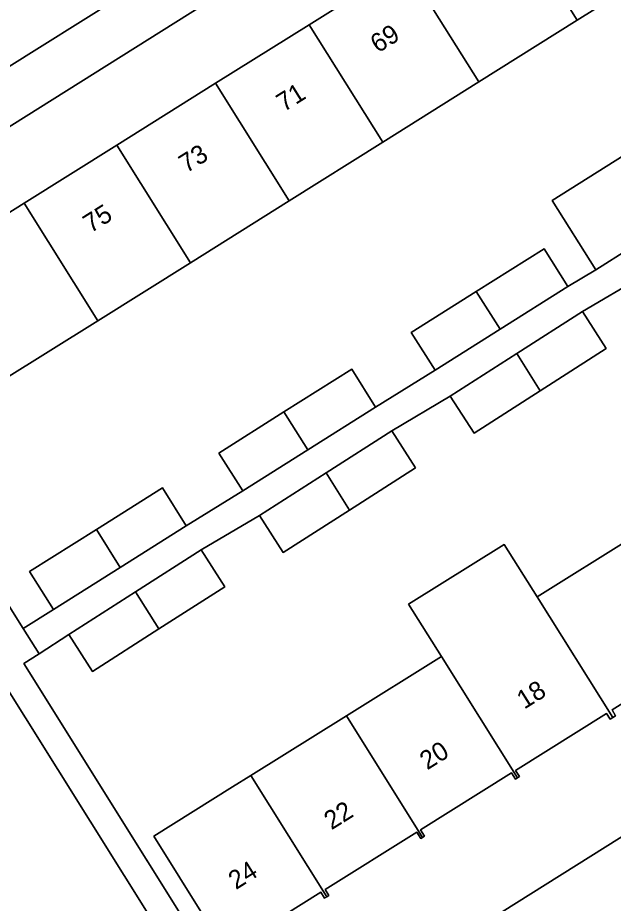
# Model space of a CAD drawing. Extents: x 160077 to 160948, y 386481 to 387498.
# Drawn here: x 160267.39 to 160299.46, y 387095.89 to 387143.58 of the extents above; entities that cross this region are included whole.
import ezdxf

# ---------------------------------------------------------------- set-up
doc = ezdxf.new("R2010")
doc.units = 0
for name, color, linetype in [('IMGEO_Erf', 7, 'Continuous'), ('IMGEO_Groenvoorziening', 7, 'Continuous'), ('IMGEO_Pand', 7, 'Continuous'), ('IMGEO_Pand_nummerreeks', 7, 'Continuous'), ('IMGEO_Parkeervlak_open', 7, 'Continuous'), ('IMGEO_Voetpad_open', 7, 'Continuous')]:
    doc.layers.add(name, color=color, linetype=linetype)

msp = doc.modelspace()

# ---------------------------------------------------------------- linework, layer by layer
at = {"layer": 'IMGEO_Erf'}
for points in [[(160296.499, 387156.3), (160255.281, 387130.409), (160257.386, 387127.102), (160262.53, 387130.326), (160267.734, 387133.588), (160272.723, 387136.714), (160278.049, 387140.052), (160283.079, 387143.205), (160288.249, 387146.446)], [(160302.552, 387146.604), (160297.518, 387143.449), (160292.212, 387140.123), (160287.042, 387136.883), (160282.011, 387133.73), (160276.686, 387130.392), (160271.698, 387127.266), (160266.493, 387124.003)], [(160261.349, 387120.779), (160267.688, 387110.692), (160269.311, 387111.715), (160268.027, 387113.752), (160271.626, 387116.021), (160275.184, 387118.265), (160276.468, 387116.228), (160279.504, 387118.104), (160278.22, 387120.141), (160281.726, 387122.352), (160285.377, 387124.654), (160286.661, 387122.617), (160289.86, 387124.595), (160288.576, 387126.632), (160292.082, 387128.843), (160295.733, 387131.145), (160297.017, 387129.108), (160298.519, 387130.015), (160296.174, 387133.735), (160301.501, 387137.095)], [(160300.981, 387129.632), (160297.804, 387127.766), (160299.081, 387125.774), (160295.522, 387123.491), (160291.96, 387121.206), (160290.683, 387123.197), (160287.534, 387121.342), (160288.811, 387119.35), (160285.252, 387117.067), (160281.69, 387114.782), (160280.413, 387116.773), (160277.266, 387114.933), (160278.543, 387112.941), (160274.998, 387110.667), (160271.422, 387108.373), (160270.145, 387110.364), (160268.541, 387109.335), (160267.725, 387108.811), (160280.982, 387087.594), (160343.569, 387126.901)], [(160278.833, 387092.92), (160274.718, 387099.506), (160278.959, 387102.156), (160279.935, 387102.766), (160285.087, 387105.985), (160290.2, 387109.18), (160288.434, 387111.995), (160293.59, 387115.217), (160295.356, 387112.402), (160300.473, 387115.599)], [(160304.261, 387109.353), (160299.391, 387106.304), (160299.584, 387105.994), (160299.435, 387105.901), (160299.285, 387105.807), (160299.092, 387106.116), (160294.195, 387103.05), (160294.406, 387102.714), (160294.298, 387102.647), (160294.189, 387102.579), (160293.979, 387102.915), (160289.08, 387099.848), (160289.293, 387099.507), (160289.191, 387099.444), (160289.092, 387099.382), (160288.879, 387099.722), (160283.944, 387096.633), (160284.145, 387096.31), (160284.03, 387096.238), (160283.916, 387096.167), (160283.715, 387096.49), (160278.842, 387093.439)]]:
    msp.add_lwpolyline(points, dxfattribs=at)
at = {"layer": 'IMGEO_Groenvoorziening'}
msp.add_lwpolyline([(160250.939, 387127.668), (160246.937, 387125.176), (160273.417, 387082.895), (160277.504, 387085.429), (160277.697, 387085.561), (160277.877, 387085.709), (160278.043, 387085.873), (160278.194, 387086.051), (160278.329, 387086.242), (160278.445, 387086.444), (160278.544, 387086.656), (160278.623, 387086.876), (160278.682, 387087.102), (160278.72, 387087.332), (160278.738, 387087.565), (160278.735, 387087.798), (160278.712, 387088.03), (160278.667, 387088.26), (160278.602, 387088.484), (160278.518, 387088.702), (160278.414, 387088.911), (160278.341, 387089.035), (160266.048, 387108.664)], dxfattribs=at)
at = {"layer": 'IMGEO_Pand'}
for points in [[(160298.589, 387152.926), (160293.555, 387149.771), (160297.518, 387143.449), (160302.552, 387146.604)], [(160292.212, 387140.123), (160297.518, 387143.449), (160293.555, 387149.771), (160288.249, 387146.446)], [(160287.042, 387136.883), (160292.212, 387140.123), (160288.249, 387146.446), (160283.079, 387143.205)], [(160283.079, 387143.205), (160278.049, 387140.052), (160282.011, 387133.73), (160287.042, 387136.883)], [(160276.686, 387130.392), (160282.011, 387133.73), (160278.049, 387140.052), (160272.723, 387136.714)], [(160303.837, 387133.369), (160302.558, 387135.409), (160301.501, 387137.095), (160296.174, 387133.735), (160298.519, 387130.015), (160300.336, 387131.161)], [(160272.723, 387136.714), (160267.734, 387133.588), (160271.698, 387127.266), (160276.686, 387130.392)], [(160266.493, 387124.003), (160271.698, 387127.266), (160267.734, 387133.588), (160262.53, 387130.326)], [(160297.017, 387129.108), (160295.733, 387131.145), (160292.082, 387128.843), (160293.361, 387126.803)], [(160288.576, 387126.632), (160289.86, 387124.595), (160293.361, 387126.803), (160292.082, 387128.843)], [(160299.081, 387125.774), (160297.804, 387127.766), (160294.265, 387125.495), (160295.522, 387123.491)], [(160290.683, 387123.197), (160291.96, 387121.206), (160295.522, 387123.491), (160294.265, 387125.495)], [(160286.661, 387122.617), (160285.377, 387124.654), (160281.726, 387122.352), (160283.005, 387120.312)], [(160278.22, 387120.141), (160279.504, 387118.104), (160283.005, 387120.312), (160281.726, 387122.352)], [(160288.811, 387119.35), (160287.534, 387121.342), (160283.995, 387119.071), (160285.252, 387117.067)], [(160280.413, 387116.773), (160281.69, 387114.782), (160285.252, 387117.067), (160283.995, 387119.071)], [(160272.905, 387113.981), (160276.468, 387116.228), (160275.184, 387118.265), (160271.626, 387116.021)], [(160271.626, 387116.021), (160268.027, 387113.752), (160269.311, 387111.715), (160272.905, 387113.981)], [(160300.473, 387115.599), (160295.356, 387112.402), (160299.435, 387105.901), (160299.584, 387105.994), (160299.391, 387106.304), (160304.261, 387109.353), (160304.441, 387109.065), (160304.535, 387109.124)], [(160274.998, 387110.667), (160278.543, 387112.941), (160277.266, 387114.933), (160273.741, 387112.671)], [(160295.356, 387112.402), (160293.59, 387115.217), (160288.434, 387111.995), (160290.2, 387109.18), (160294.298, 387102.647), (160294.406, 387102.714), (160294.195, 387103.05), (160299.092, 387106.116), (160299.285, 387105.807), (160299.435, 387105.901)], [(160273.741, 387112.671), (160270.145, 387110.364), (160271.422, 387108.373), (160274.998, 387110.667)], [(160290.2, 387109.18), (160285.087, 387105.985), (160289.191, 387099.444), (160289.293, 387099.507), (160289.08, 387099.848), (160293.979, 387102.915), (160294.189, 387102.579), (160294.298, 387102.647)], [(160285.087, 387105.985), (160279.935, 387102.766), (160284.03, 387096.238), (160284.145, 387096.31), (160283.944, 387096.633), (160288.879, 387099.722), (160289.092, 387099.382), (160289.191, 387099.444)], [(160279.935, 387102.766), (160278.959, 387102.156), (160274.718, 387099.506), (160278.833, 387092.92), (160279.073, 387093.07), (160278.842, 387093.439), (160283.715, 387096.49), (160283.916, 387096.167), (160284.03, 387096.238)]]:
    msp.add_lwpolyline(points, close=True, dxfattribs=at)
at = {"layer": 'IMGEO_Parkeervlak_open'}
msp.add_lwpolyline([(160262.765, 387147.16), (160266.781, 387140.866), (160272.691, 387144.583)], dxfattribs=at)
at = {"layer": 'IMGEO_Voetpad_open'}
for points in [[(160292.647, 387157.133), (160281.95, 387150.406), (160272.691, 387144.583), (160266.781, 387140.866), (160264.195, 387139.299), (160246.804, 387128.394), (160245.754, 387127.736), (160241.091, 387124.7), (160236.718, 387121.973), (160238.871, 387120.28), (160242.235, 387122.407), (160246.937, 387125.176), (160250.939, 387127.668), (160255.281, 387130.409), (160296.499, 387156.3)], [(160364.462, 387140.04), (160355.514, 387134.432), (160344.857, 387127.71), (160343.569, 387126.901), (160280.982, 387087.594), (160267.725, 387108.811), (160268.541, 387109.335), (160267.688, 387110.692), (160261.349, 387120.779), (160257.386, 387127.102), (160255.281, 387130.409), (160250.939, 387127.668)], [(160300.336, 387131.161), (160298.519, 387130.015), (160297.017, 387129.108), (160293.361, 387126.803), (160289.86, 387124.595), (160286.661, 387122.617), (160283.005, 387120.312), (160279.504, 387118.104), (160276.468, 387116.228), (160272.905, 387113.981), (160269.311, 387111.715), (160267.688, 387110.692), (160268.541, 387109.335), (160270.145, 387110.364), (160273.741, 387112.671), (160277.266, 387114.933), (160280.413, 387116.773), (160283.995, 387119.071), (160287.534, 387121.342), (160290.683, 387123.197), (160294.265, 387125.495), (160297.804, 387127.766), (160300.981, 387129.632)], [(160254.52, 387127.019), (160266.048, 387108.664), (160278.341, 387089.035)]]:
    msp.add_lwpolyline(points, dxfattribs=at)

# ---------------------------------------------------------------- texts
at = {"layer": 'IMGEO_Pand_nummerreeks'}
for s, rotation, p in [('69', 32.0777, (160286.784, 387141.657)), ('71', 32.0777, (160281.723, 387138.486)), ('73', 32.0777, (160276.473, 387135.194)), ('75', 32.0777, (160271.317, 387131.963)), ('18', 32.0455, (160294.665, 387106.319)), ('20', 32.0455, (160289.439, 387103.046)), ('22', 32.0455, (160284.286, 387099.82)), ('24', 32.0455, (160279.139, 387096.599))]:
    msp.add_text(s, height=1, rotation=rotation, dxfattribs=at).set_placement(p)

doc.saveas('drawing.dxf')
